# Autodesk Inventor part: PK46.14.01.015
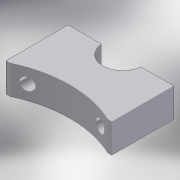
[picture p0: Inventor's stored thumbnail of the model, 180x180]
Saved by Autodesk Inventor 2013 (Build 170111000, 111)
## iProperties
Created: 2005-03
Part Number: PK46.14.01.015
Document SubType Name: Modeling
Designer: elarisa
Manufacturer: Standard
Standards Organization: Custom
Density: 1 g/cm^3
Material: Generic
Author: elarisa
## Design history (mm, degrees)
sketch "Эскиз1"
  geometry: L1 (-27.835, -10.971)-(-27.835, 23.029); L2 (30.165, 23.029)-(30.165, -10.971); L3 (30.165, -10.971)-(27.998, -10.971); L4 (-25.668, -10.971)-(-27.835, -10.971); L5 (-27.835, 23.029)-(-9.789, 23.029); L6 (12.119, 23.029)-(30.165, 23.029); A1 r 11 centre (1.165, 24.029) between (-9.789, 23.029) and (12.119, 23.029); A2 r 63 centre (1.165, -67.971) between (27.998, -10.971) and (-25.668, -10.971)
  constraints: 12 end point, 5 parallel, 4 point on circle, 2 centre point, 2 collinear, 2 perpendicular, 1 vertical
  dimensions: "d0" = 1 distance from line of L5 A1.centre; "d1" = 11 radius of A1; "d2" = 58 distance between parallel lines of L2 L1; "d3" = 29 distance from line of L1 A1.centre; "d4" = 29 distance from line of L1 A2.centre; "d5" = 63 radius of A2; "d6" = 34 distance of L1.start L1.end; "d7" = 6 distance edge to line of A2 L4
extrude "Выдавливание1" new body sketch "Эскиз1" distance "d8" = 16; taper "d9" = 0 deg
sketch "Эскиз2"
  geometry: L1 (58, 0)-(58, -16) reference; L2 (39.954, -16)-(58, -16) reference; 2 further points
  dimensions: "d10" = 40 distance of point (49, -8) point (9, -8); "d11" = 9 distance from line of L1 point (49, -8); "d12" = 8 distance from line of L2 point (49, -8); "d13" = 0 vertical distance of point (49, -8) point (9, -8)
hole "Отверстие1" sketch "Эскиз2" diameter "d14" = 6.647; stored, may be unused: countersink angle "d18" = 90 deg, drill point angle "d20" = 118 deg; dims "d15" = 20, "d16" = 10.5, "d17" = 2, "d19" = 20
body "Solid1"
